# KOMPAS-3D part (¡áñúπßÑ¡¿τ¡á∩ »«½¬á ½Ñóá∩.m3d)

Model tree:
1. Эскиз:1
2. Операция выдавливания:1
     Расстояние 1 = 2
3. Эскиз:2
4. Операция выдавливания:2
     Расстояние 1 = 3
5. Эскиз:3
6. Операция выдавливания:3
     Расстояние 1 = 10
7. Эскиз:9
8. Вырезать элемент выдавливания:4
     Расстояние 1 = 2
9. Эскиз:13
10. Операция выдавливания:7
     Расстояние 1 = 7; Расстояние 2 = 4.9
11. Эскиз:14
12. Операция выдавливания:8
     Расстояние 1 = 17; Расстояние 2 = 4.9
13. Эскиз:15
14. Операция выдавливания:9
     Расстояние 1 = 2; Расстояние 2 = 4.9
15. Эскиз:16
16. Вырезать элемент выдавливания:7
     Расстояние 1 = 36.4418
17. Эскиз:17
18. Вырезать элемент выдавливания:8
     Расстояние 1 = 2
19. Фаска:2
     Угол = 45; Длина 1 = 2; Длина 2 = 2
20. Эскиз:18
21. Вырезать элемент выдавливания:9
     Расстояние 1 = 2
22. Эскиз:19
23. Вырезать элемент выдавливания:10
     Расстояние 1 = 1
24. Эскиз:20
25. Вырезать элемент выдавливания:11
     Расстояние 1 = 200
26. Эскиз:21
27. Операция выдавливания:10
     Расстояние 1 = 10; Расстояние 2 = 36.8
28. Эскиз:22
29. Вырезать элемент выдавливания:12
     Расстояние 1 = 1
30. Скругление:1
     Радиус = 2

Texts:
  надгусеничная полка левая
  Сплав АЛ8  ГОСТ 1583-93
  stalker61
